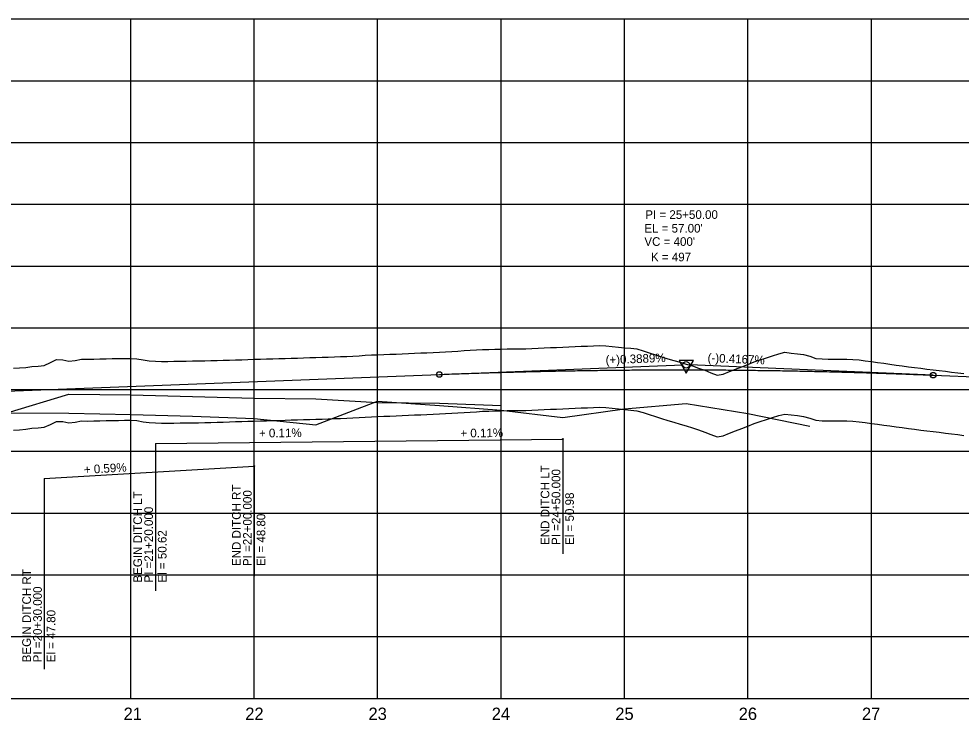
# Model space of a CAD drawing. Extents: x 2345490 to 2436403, y 465165 to 573888.
# Drawn here: x 2382331 to 2383094, y 557766 to 558334 of the extents above; entities that cross this region are included whole.
import ezdxf

# ---------------------------------------------------------------- set-up
doc = ezdxf.new("R2010")
doc.units = 0
for name, color, linetype in [('Old_Level_1', 7, 'Continuous'), ('Old_Level_2', 7, 'Continuous'), ('Old_Level_3', 7, 'Continuous'), ('Old_Level_57', 7, 'Continuous'), ('Old_Level_62', 7, 'Continuous'), ('Old_Level_63', 7, 'Continuous')]:
    doc.layers.add(name, color=color, linetype=linetype)

msp = doc.modelspace()

# ---------------------------------------------------------------- linework, layer by layer
at = {"layer": 'Old_Level_1'}
for points in [[(2382326.5425, 558001.31675), (2382331.5425, 558001.601), (2382336.5425, 558002.057), (2382341.5425, 558002.719), (2382346.5425, 558003.0015), (2382351.5425, 558003.5645), (2382356.5425, 558005.94325), (2382361.5425, 558008.322), (2382366.5425, 558008.2755), (2382371.5425, 558007.1595), (2382376.5425, 558007.7375), (2382381.5425, 558008.74525), (2382386.5425, 558008.6005), (2382391.5425, 558008.702), (2382396.5425, 558008.8405), (2382401.5425, 558008.979), (2382406.5425, 558009.118), (2382411.5425, 558009.16725), (2382416.5425, 558009.1965), (2382421.5425, 558009.226), (2382426.5425, 558008.95975), (2382431.5425, 558008.044), (2382436.5425, 558007.33925), (2382441.5425, 558007.21075), (2382446.5425, 558006.789), (2382451.5425, 558006.89375), (2382456.5425, 558006.99), (2382461.5425, 558007.08675), (2382466.5425, 558007.18425), (2382471.5425, 558007.23), (2382476.5425, 558007.24775), (2382481.5425, 558007.39325), (2382486.5425, 558007.54), (2382491.5425, 558007.68775), (2382496.5425, 558007.837), (2382501.5425, 558007.97575), (2382506.5425, 558008.1255), (2382511.5425, 558008.2765), (2382516.5425, 558008.42875), (2382521.5425, 558008.58225), (2382526.5425, 558008.737), (2382531.5425, 558008.862), (2382536.5425, 558009.00875), (2382541.5425, 558009.15675), (2382546.5425, 558009.31125), (2382551.5425, 558009.46975), (2382556.5425, 558009.62975), (2382561.5425, 558009.7915), (2382566.5425, 558009.95825), (2382571.5425, 558010.1115), (2382576.5425, 558010.2665), (2382581.5425, 558010.42325), (2382586.5425, 558010.59125), (2382591.5425, 558010.77925), (2382596.5425, 558010.93275), (2382601.5425, 558011.11825), (2382606.5425, 558011.442), (2382611.5425, 558011.815), (2382616.5425, 558012.083), (2382621.5425, 558012.2665), (2382626.5425, 558012.45225), (2382631.5425, 558012.64025), (2382636.5425, 558012.831), (2382641.5425, 558013.024), (2382646.5425, 558013.269), (2382651.5425, 558013.5195), (2382656.5425, 558013.73375), (2382661.5425, 558013.951), (2382666.5425, 558014.17075), (2382671.5425, 558014.4275), (2382676.5425, 558014.7165), (2382681.5425, 558015.00875), (2382686.5425, 558015.304), (2382691.5425, 558015.597), (2382696.5425, 558015.8945), (2382701.5425, 558016.20425), (2382706.5425, 558016.495), (2382711.5425, 558016.6295), (2382716.5425, 558016.7655), (2382721.5425, 558016.9035), (2382726.5425, 558017.04025), (2382731.5425, 558017.0705), (2382736.5425, 558017.10275), (2382741.5425, 558017.137), (2382746.5425, 558017.3595), (2382751.5425, 558017.6255), (2382756.5425, 558017.89375), (2382761.5425, 558018.151), (2382766.5425, 558018.2795), (2382771.5425, 558018.508), (2382776.5425, 558018.797), (2382781.5425, 558019.047), (2382786.5425, 558019.18725), (2382791.5425, 558019.3475), (2382796.5425, 558019.56325), (2382801.5425, 558019.78075), (2382806.5425, 558019.49125), (2382811.5425, 558018.90925), (2382816.5425, 558018.435), (2382821.5425, 558017.95625)], [(2382821.5425, 558017.95625), (2382826.5425, 558017.4735), (2382831.5425, 558016.962), (2382836.5425, 558015.4025), (2382841.5425, 558013.82975), (2382846.5425, 558012.24475), (2382851.5425, 558010.648), (2382856.5425, 558009.05625), (2382861.5425, 558007.6185), (2382866.5425, 558006.16875), (2382871.5425, 558004.6825), (2382876.5425, 558003.22575), (2382881.5425, 558001.498), (2382886.5425, 557999.6715), (2382891.5425, 557997.73575), (2382896.5425, 557995.78775), (2382901.5425, 557996.65625), (2382906.5425, 557998.6755), (2382911.5425, 558000.5625), (2382916.5425, 558002.50375), (2382921.5425, 558004.4935), (2382926.5425, 558006.4955), (2382931.5425, 558008.26475), (2382936.5425, 558009.80975), (2382941.5425, 558011.36625), (2382946.5425, 558012.97575), (2382951.5425, 558014.2955), (2382956.5425, 558013.65175), (2382961.5425, 558013.00675), (2382966.5425, 558012.36025), (2382971.5425, 558011.014), (2382976.5425, 558009.30475), (2382981.5425, 558008.8615), (2382986.5425, 558008.81725), (2382991.5425, 558008.7735), (2382996.5425, 558008.73), (2383001.5425, 558008.687), (2383006.5425, 558008.556), (2383011.5425, 558008.08625), (2383016.5425, 558007.40225), (2383021.5425, 558006.71775), (2383026.5425, 558006.03275), (2383031.5425, 558005.3475), (2383036.5425, 558004.662), (2383041.5425, 558003.976), (2383046.5425, 558003.28975), (2383051.5425, 558002.60325), (2383056.5425, 558001.9795), (2383061.5425, 558001.35625), (2383066.5425, 558000.73225), (2383071.5425, 558000.10825), (2383076.5425, 557999.48375), (2383081.5425, 557998.85875), (2383086.5425, 557998.23325), (2383091.5425, 557997.60775), (2383096.5425, 557996.99325)]]:
    msp.add_lwpolyline(points, dxfattribs=at)
at = {"layer": 'Old_Level_2'}
for p, q in [((2382671.5425, 558046.335), (2382868.79475, 558054.006)), ((2383071.5425, 558045.7795), (2382874.29025, 558053.9985)), ((2381971.5425, 558019.113), (2382671.5425, 558046.335)), ((2383071.5425, 558045.7795), (2383361.5425, 558033.69625))]:
    msp.add_line(p, q, dxfattribs=at)
msp.add_lwpolyline([(2382877.43325, 558057.51575), (2382865.69075, 558057.50125), (2382871.57425, 558047.383)], close=True, dxfattribs=at)
for centre, radius in [((2382871.5425, 558054.113), 2.75), ((2382671.5425, 558046.335), 2.25), ((2383071.5425, 558045.7795), 2.25)]:
    msp.add_circle(centre, radius, dxfattribs=at)
msp.add_spline([(2382671.5425, 558046.335), (2382679.5425, 558046.63975), (2382687.5425, 558046.9315), (2382695.5425, 558047.2105), (2382703.5425, 558047.4765), (2382711.5425, 558047.7295), (2382719.5425, 558047.96975), (2382727.5425, 558048.197), (2382735.5425, 558048.4115), (2382743.5425, 558048.613), (2382751.5425, 558048.80175), (2382759.5425, 558048.9775), (2382767.5425, 558049.1405), (2382775.5425, 558049.2905), (2382783.5425, 558049.4275), (2382791.5425, 558049.55175), (2382799.5425, 558049.663), (2382807.5425, 558049.7615), (2382815.5425, 558049.847), (2382823.5425, 558049.91975), (2382831.5425, 558049.9795), (2382839.5425, 558050.0265), (2382847.5425, 558050.0605), (2382855.5425, 558050.0815), (2382863.5425, 558050.08975), (2382871.5425, 558050.085), (2382879.5425, 558050.0675), (2382887.5425, 558050.037), (2382895.5425, 558049.99375), (2382903.5425, 558049.9375), (2382911.5425, 558049.8685), (2382919.5425, 558049.7865), (2382927.5425, 558049.6915), (2382935.5425, 558049.58375), (2382943.5425, 558049.463), (2382951.5425, 558049.3295), (2382959.5425, 558049.183), (2382967.5425, 558049.02375), (2382975.5425, 558048.8515), (2382983.5425, 558048.6665), (2382991.5425, 558048.4685), (2382999.5425, 558048.2575), (2383007.5425, 558048.03375), (2383015.5425, 558047.797), (2383023.5425, 558047.5475), (2383031.5425, 558047.285), (2383039.5425, 558047.00975), (2383047.5425, 558046.7215), (2383055.5425, 558046.4205), (2383063.5425, 558046.1065), (2383071.5425, 558045.7795)], degree=3, dxfattribs=at)
at = {"layer": 'Old_Level_3'}
for p, q in [((2382441.5425, 557990.313), (2382771.5425, 557993.913)), ((2382771.5425, 557993.913), (2382771.5425, 557901.14511)), ((2382441.5425, 557990.313), (2382441.5425, 557871.06918)), ((2382351.5425, 557962.113), (2382521.5425, 557972.113)), ((2382521.5425, 557972.113), (2382521.5425, 557882.91727)), ((2382351.5425, 557962.113), (2382351.5425, 557807.72745))]:
    msp.add_line(p, q, dxfattribs=at)
for centre in [(2382771.5425, 557993.913), (2382521.5425, 557972.113)]:
    msp.add_circle(centre, 0.5, dxfattribs=at)
at = {"layer": 'Old_Level_57'}
for p, q in [((2381271.54275, 558334.11325), (2393041.55275, 558334.11325)), ((2382421.54225, 557784.21325), (2382421.54225, 558334.21325)), ((2382421.54225, 557784.11325), (2382421.54225, 558334.11325)), ((2382521.54225, 557784.21325), (2382521.54225, 558334.21325)), ((2382521.54225, 557784.11325), (2382521.54225, 558334.11325)), ((2382621.54225, 557784.21325), (2382621.54225, 558334.21325)), ((2382621.54225, 557784.11325), (2382621.54225, 558334.11325)), ((2382721.54225, 557784.21325), (2382721.54225, 558334.21325)), ((2382721.54225, 557784.11325), (2382721.54225, 558334.11325)), ((2382821.54225, 557784.21325), (2382821.54225, 558334.21325)), ((2382821.54225, 557784.11325), (2382821.54225, 558334.11325)), ((2382921.54225, 557784.21325), (2382921.54225, 558334.21325)), ((2382921.54225, 557784.11325), (2382921.54225, 558334.11325)), ((2383021.54225, 557784.21325), (2383021.54225, 558334.21325)), ((2383021.54225, 557784.11325), (2383021.54225, 558334.11325)), ((2381271.54275, 558284.11325), (2393041.55275, 558284.11325)), ((2381271.54275, 558234.11325), (2393041.55275, 558234.11325)), ((2381271.54275, 558184.11325), (2393041.55275, 558184.11325)), ((2381271.54275, 558134.11325), (2393041.55275, 558134.11325)), ((2381271.54275, 558084.11325), (2393041.55275, 558084.11325)), ((2381271.5425, 558034.11325), (2393041.55275, 558034.11325)), ((2381271.54275, 557984.11325), (2393041.55275, 557984.11325)), ((2381271.5425, 557934.11325), (2393041.55275, 557934.11325)), ((2381271.54275, 557884.11325), (2393041.55275, 557884.11325)), ((2381271.5425, 557834.11325), (2393041.55275, 557834.11325)), ((2381271.54275, 557784.11325), (2393041.55275, 557784.11325))]:
    msp.add_line(p, q, dxfattribs=at)
at = {"layer": 'Old_Level_62'}
for points in [[(2382326.5425, 558051.32275), (2382331.5425, 558051.607), (2382336.5425, 558052.063), (2382341.5425, 558052.725), (2382346.5425, 558053.0075), (2382351.5425, 558053.5705), (2382356.5425, 558055.94925), (2382361.5425, 558058.328), (2382366.5425, 558058.2815), (2382371.5425, 558057.1655), (2382376.5425, 558057.7435), (2382381.5425, 558058.75125), (2382386.5425, 558058.6065), (2382391.5425, 558058.708), (2382396.5425, 558058.8465), (2382401.5425, 558058.985), (2382406.5425, 558059.124), (2382411.5425, 558059.17325), (2382416.5425, 558059.2025), (2382421.5425, 558059.232), (2382426.5425, 558058.96575), (2382431.5425, 558058.05), (2382436.5425, 558057.34525), (2382441.5425, 558057.21675), (2382446.5425, 558056.795), (2382451.5425, 558056.89975), (2382456.5425, 558056.996), (2382461.5425, 558057.09275), (2382466.5425, 558057.19025), (2382471.5425, 558057.236), (2382476.5425, 558057.25375), (2382481.5425, 558057.39925), (2382486.5425, 558057.546), (2382491.5425, 558057.69375), (2382496.5425, 558057.843), (2382501.5425, 558057.98175), (2382506.5425, 558058.1315), (2382511.5425, 558058.2825), (2382516.5425, 558058.43475), (2382521.5425, 558058.58825), (2382526.5425, 558058.743), (2382531.5425, 558058.868), (2382536.5425, 558059.01475), (2382541.5425, 558059.16275), (2382546.5425, 558059.31725), (2382551.5425, 558059.47575), (2382556.5425, 558059.63575), (2382561.5425, 558059.7975), (2382566.5425, 558059.96425), (2382571.5425, 558060.1175), (2382576.5425, 558060.2725), (2382581.5425, 558060.42925), (2382586.5425, 558060.59725), (2382591.5425, 558060.78525), (2382596.5425, 558060.93875), (2382601.5425, 558061.12425), (2382606.5425, 558061.448), (2382611.5425, 558061.821), (2382616.5425, 558062.089), (2382621.5425, 558062.2725), (2382626.5425, 558062.45825), (2382631.5425, 558062.64625), (2382636.5425, 558062.837), (2382641.5425, 558063.03), (2382646.5425, 558063.275), (2382651.5425, 558063.5255), (2382656.5425, 558063.73975), (2382661.5425, 558063.957), (2382666.5425, 558064.17675), (2382671.5425, 558064.4335), (2382676.5425, 558064.7225), (2382681.5425, 558065.01475), (2382686.5425, 558065.31), (2382691.5425, 558065.603), (2382696.5425, 558065.9005), (2382701.5425, 558066.21025), (2382706.5425, 558066.501), (2382711.5425, 558066.6355), (2382716.5425, 558066.7715), (2382721.5425, 558066.9095), (2382726.5425, 558067.04625), (2382731.5425, 558067.0765), (2382736.5425, 558067.10875), (2382741.5425, 558067.143), (2382746.5425, 558067.3655), (2382751.5425, 558067.6315), (2382756.5425, 558067.89975), (2382761.5425, 558068.157), (2382766.5425, 558068.2855), (2382771.5425, 558068.514), (2382776.5425, 558068.803), (2382781.5425, 558069.053), (2382786.5425, 558069.19325), (2382791.5425, 558069.3535), (2382796.5425, 558069.56925), (2382801.5425, 558069.78675), (2382806.5425, 558069.49725), (2382811.5425, 558068.91525), (2382816.5425, 558068.441), (2382821.5425, 558067.96225)], [(2382821.5425, 558067.96225), (2382826.5425, 558067.4795), (2382831.5425, 558066.968), (2382836.5425, 558065.4085), (2382841.5425, 558063.83575), (2382846.5425, 558062.25075), (2382851.5425, 558060.654), (2382856.5425, 558059.06225), (2382861.5425, 558057.6245), (2382866.5425, 558056.17475), (2382871.5425, 558054.6885), (2382876.5425, 558053.23175), (2382881.5425, 558051.504), (2382886.5425, 558049.6775), (2382891.5425, 558047.74175), (2382896.5425, 558045.79375), (2382901.5425, 558046.66225), (2382906.5425, 558048.6815), (2382911.5425, 558050.5685), (2382916.5425, 558052.50975), (2382921.5425, 558054.4995), (2382926.5425, 558056.5015), (2382931.5425, 558058.27075), (2382936.5425, 558059.81575), (2382941.5425, 558061.37225), (2382946.5425, 558062.98175), (2382951.5425, 558064.3015), (2382956.5425, 558063.65775), (2382961.5425, 558063.01275), (2382966.5425, 558062.36625), (2382971.5425, 558061.02), (2382976.5425, 558059.31075), (2382981.5425, 558058.8675), (2382986.5425, 558058.82325), (2382991.5425, 558058.7795), (2382996.5425, 558058.736), (2383001.5425, 558058.693), (2383006.5425, 558058.562), (2383011.5425, 558058.09225), (2383016.5425, 558057.40825), (2383021.5425, 558056.72375), (2383026.5425, 558056.03875), (2383031.5425, 558055.3535), (2383036.5425, 558054.668), (2383041.5425, 558053.982), (2383046.5425, 558053.29575), (2383051.5425, 558052.60925), (2383056.5425, 558051.9855), (2383061.5425, 558051.36225), (2383066.5425, 558050.73825), (2383071.5425, 558050.11425), (2383076.5425, 558049.48975), (2383081.5425, 558048.86475), (2383086.5425, 558048.23925), (2383091.5425, 558047.61375), (2383096.5425, 558046.99925)], [(2381921.5425, 558014.613), (2381971.5425, 558017.013), (2382021.5425, 558016.713), (2382071.5425, 558015.713), (2382121.5425, 558015.613), (2382171.5425, 558016.013), (2382221.5425, 558016.113), (2382271.5425, 558015.713), (2382321.5425, 558015.213), (2382371.5425, 558030.313), (2382421.5425, 558029.713), (2382471.5425, 558028.413), (2382521.5425, 558027.213), (2382571.5425, 558026.613), (2382621.5425, 558023.713), (2382671.5425, 558023.013), (2382721.5425, 558021.313)], [(2381921.5425, 558018.913), (2381971.5425, 558019.113), (2382021.5425, 558018.313), (2382071.5425, 558017.413), (2382121.5425, 558016.713), (2382171.5425, 558016.113), (2382221.5425, 558016.013), (2382271.5425, 558016.013), (2382321.5425, 558015.213), (2382371.5425, 558015.013), (2382421.5425, 558013.913), (2382471.5425, 558012.513), (2382521.5425, 558010.713), (2382571.5425, 558005.613), (2382621.5425, 558024.813), (2382671.5425, 558021.113), (2382721.5425, 558017.413), (2382771.5425, 558011.613), (2382821.5425, 558018.413), (2382871.5425, 558022.913), (2382921.5425, 558014.613), (2382971.5425, 558004.513)]]:
    msp.add_lwpolyline(points, dxfattribs=at)
at = {"layer": 'Old_Level_63'}
msp.add_line((2381321.5425, 557784.113), (2393019.104, 557784.113), dxfattribs=at)

# ---------------------------------------------------------------- texts
at = {"layer": 'Old_Level_1'}
for s, p in [('21', (2382415.7685, 557766.613)), ('22', (2382514.31675, 557766.613)), ('23', (2382614.1515, 557766.613)), ('24', (2382713.994, 557766.613)), ('25', (2382814.0865, 557766.613)), ('26', (2382914.0275, 557766.613)), ('27', (2383013.885, 557766.613))]:
    msp.add_text(s, height=10.000001, dxfattribs=at).set_placement(p)
at = {"layer": 'Old_Level_2'}
for s, height, p in [('PI = 25+50.00', 7.0000005, (2382838.36025, 558172.265)), ("EL = 57.00'", 7.0000005, (2382837.56225, 558161.19325)), ("VC = 400'", 7.000001, (2382837.61575, 558150.4255)), ('K = 497', 7.000001, (2382842.9395, 558137.92075))]:
    msp.add_text(s, height=height, dxfattribs=at).set_placement(p)
for s, rotation, p in [('(+)0.3889%', 2.22704722, (2382806.34625, 558054.5795)), ('(-)0.4167%', 357.61405556, (2382888.72775, 558056.3995))]:
    msp.add_text(s, height=7.000001, rotation=rotation, dxfattribs=at).set_placement(p)
at = {"layer": 'Old_Level_3'}
for s, height, rotation, p in [('+ 0.11%', 7.000001, 0.62501944, (2382525.45594, 557995.30727)), ('+ 0.11%', 7.000001, 0.62501944, (2382688.59506, 557995.30727)), ('+ 0.59%', 7.000001, 3.36646111, (2382383.80539, 557965.7638)), ('END DITCH LT', 7.0000005, 90, (2382760.6686, 557908.31478)), ('PI =24+50.000', 7.0000005, 90, (2382769.5425, 557908.31478)), ('END DITCH RT', 7.0000005, 90, (2382510.6686, 557891.19489)), ('BEGIN DITCH LT', 7.0000005, 90, (2382430.6686, 557877.82872)), ('PI =22+00.000', 7.0000005, 90, (2382519.5425, 557891.19489)), ('El = 50.98', 7.000001, 90, (2382780.5425, 557908.31478)), ('PI =21+20.000', 7.0000005, 90, (2382439.5425, 557877.82872)), ('El = 48.80', 7.000001, 90, (2382530.5425, 557891.19489)), ('El = 50.62', 7.000001, 90, (2382450.5425, 557877.82872)), ('BEGIN DITCH RT', 7.0000005, 90, (2382340.6686, 557813.29621)), ('PI =20+30.000', 7.0000005, 90, (2382349.5425, 557813.29621)), ('El = 47.80', 7.000001, 90, (2382360.5425, 557813.29621))]:
    msp.add_text(s, height=height, rotation=rotation, dxfattribs=at).set_placement(p)

doc.saveas('drawing.dxf')
